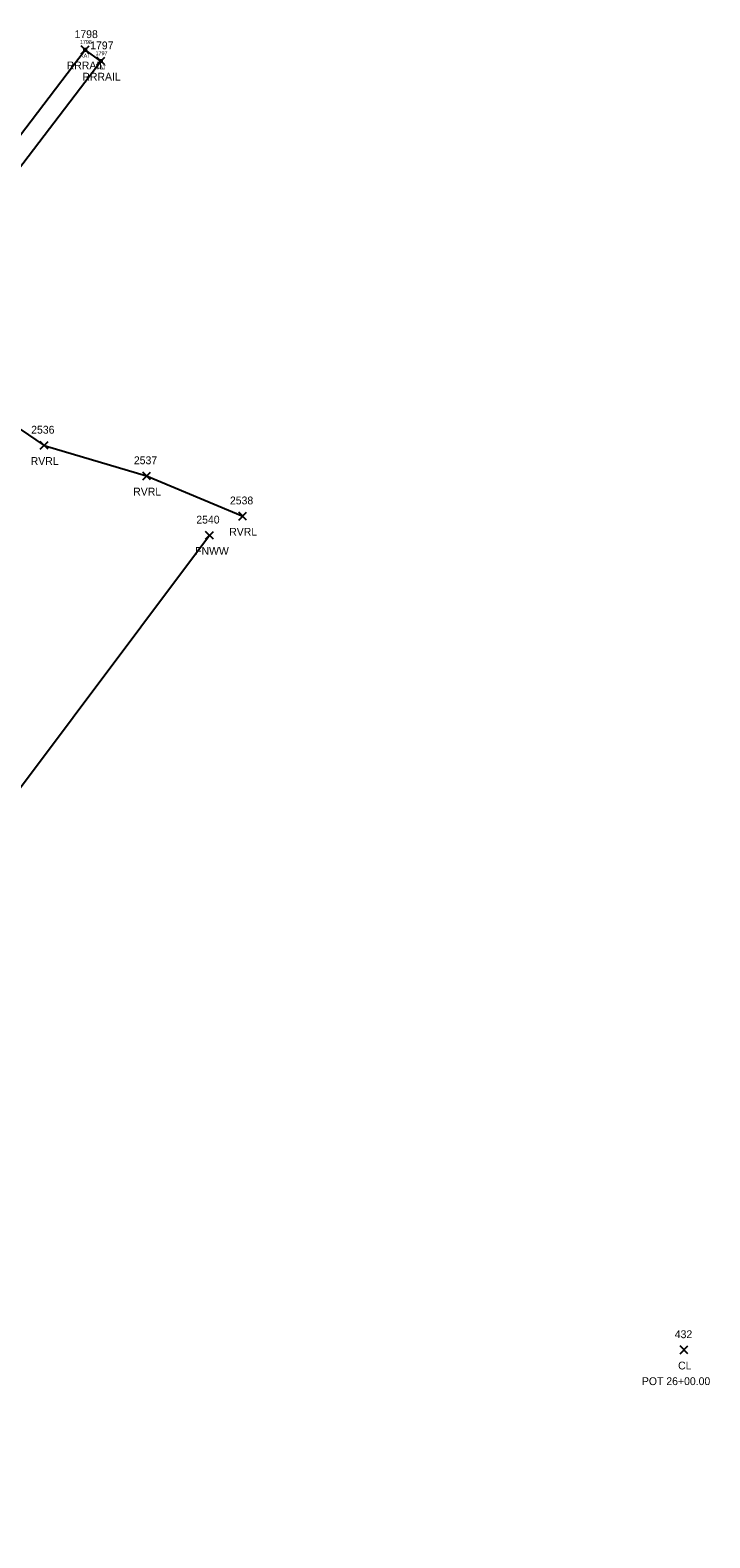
# Model space of a CAD drawing. Extents: x 1767353 to 1772625, y 740790 to 747702.
# Drawn here: x 1772451.2 to 1772625, y 747316.1 to 747701.7 of the extents above; entities that cross this region are included whole.
import ezdxf

# ---------------------------------------------------------------- set-up
doc = ezdxf.new("R2010")
doc.units = 0
for name, color, linetype in [('A_A', 7, 'Continuous'), ('A_C', 7, 'Continuous'), ('A_I', 7, 'Continuous'), ('A_TIC', 7, 'Continuous'), ('B_A', 7, 'Continuous'), ('B_I', 7, 'Continuous'), ('B_TIC', 7, 'Continuous'), ('BSUBM', 7, 'Continuous'), ('L_A', 7, 'Continuous'), ('L_I', 7, 'Continuous'), ('L_TIC', 7, 'Continuous'), ('LAWE', 7, 'Continuous'), ('LFNC', 7, 'Continuous'), ('R_A', 7, 'Continuous'), ('R_I', 7, 'Continuous'), ('R_TIC', 7, 'Continuous'), ('RR', 7, 'Continuous')]:
    doc.layers.add(name, color=color, linetype=linetype)

msp = doc.modelspace()

# ---------------------------------------------------------------- linework, layer by layer
at = {"layer": 'A_TIC'}
for points in [[(1772617.36, 747363.21), (1772619.36, 747365.21)], [(1772619.36, 747363.21), (1772617.36, 747365.21)]]:
    msp.add_lwpolyline(points, dxfattribs=at)
at = {"layer": 'B_TIC'}
for p, q in [((1772465.26, 747696.66), (1772465.33, 747696.66)), ((1772469.26, 747693.79), (1772469.33, 747693.79))]:
    msp.add_line(p, q, dxfattribs=at)
for points in [[(1772464.76, 747696.66), (1772465.76, 747696.66)], [(1772465.26, 747696.16), (1772465.26, 747697.16)], [(1772468.76, 747693.79), (1772469.76, 747693.79)], [(1772469.26, 747693.29), (1772469.26, 747694.29)]]:
    msp.add_lwpolyline(points, dxfattribs=at)
at = {"layer": 'BSUBM'}
msp.add_lwpolyline([(1772469.26, 747693.79), (1772465.26, 747696.66)], dxfattribs=at)
at = {"layer": 'L_TIC'}
for points in [[(1772453.79, 747594.51), (1772455.79, 747596.51)], [(1772455.79, 747594.51), (1772453.79, 747596.51)], [(1772479.99, 747586.69), (1772481.99, 747588.69)], [(1772481.99, 747586.69), (1772479.99, 747588.69)], [(1772504.54, 747576.42), (1772506.54, 747578.42)], [(1772506.54, 747576.42), (1772504.54, 747578.42)], [(1772496.04, 747571.52), (1772498.04, 747573.52)], [(1772498.04, 747571.52), (1772496.04, 747573.52)]]:
    msp.add_lwpolyline(points, dxfattribs=at)
at = {"layer": 'LAWE'}
msp.add_lwpolyline([(1772429.31, 747618.42), (1772438.46, 747606.53), (1772454.79, 747595.51), (1772480.99, 747587.69), (1772505.54, 747577.42)], dxfattribs=at)
at = {"layer": 'LFNC'}
msp.add_lwpolyline([(1772375.15, 747411.53), (1772444.65, 747502.58), (1772497.04, 747572.52)], dxfattribs=at)
at = {"layer": 'R_TIC'}
for points in [[(1772464.26, 747695.66), (1772466.26, 747697.66)], [(1772466.26, 747695.66), (1772464.26, 747697.66)], [(1772468.26, 747692.79), (1772470.26, 747694.79)], [(1772470.26, 747692.79), (1772468.26, 747694.79)]]:
    msp.add_lwpolyline(points, dxfattribs=at)
at = {"layer": 'RR'}
for points in [[(1771960.76, 746895.46), (1771976.57, 746936.04), (1771991.76, 746972.7), (1772003.71, 747000.43), (1772025.97, 747048.7), (1772044.45, 747086.9), (1772066.42, 747128.97), (1772087.05, 747166.47), (1772110.84, 747207.58), (1772133.43, 747244.66), (1772156.72, 747281.04), (1772175.9, 747310.14), (1772194.46, 747336.8), (1772219.05, 747370.3), (1772232.59, 747389.89), (1772256.2, 747421.67), (1772277.77, 747450.57), (1772416.44, 747632.57), (1772465.26, 747696.66)], [(1771963.49, 746888.34), (1771980.41, 746932.18), (1771994.59, 746967.04), (1772007.72, 746997.13), (1772029.49, 747045.02), (1772048.72, 747084.09), (1772070.77, 747126.16), (1772091.38, 747163.68), (1772115.23, 747205.31), (1772138.09, 747242.79), (1772160.69, 747278.1), (1772180.23, 747307.44), (1772199.65, 747335.62), (1772224.35, 747370.12), (1772238.38, 747389.48), (1772261.28, 747420.38), (1772281.38, 747447.15), (1772420.28, 747629.6), (1772469.26, 747693.79)]]:
    msp.add_lwpolyline(points, dxfattribs=at)

# ---------------------------------------------------------------- texts
at = {"layer": 'A_A'}
msp.add_text('CL', height=2, dxfattribs=at).set_placement((1772616.85, 747359.21))
at = {"layer": 'A_C'}
msp.add_text('POT 26+00.00', height=2, dxfattribs=at).set_placement((1772607.6, 747355.21))
at = {"layer": 'A_I'}
msp.add_text('432', height=2, dxfattribs=at).set_placement((1772616, 747367.21))
at = {"layer": 'B_A'}
for p in [(1772463.96, 747694.66), (1772467.96, 747691.79)]:
    msp.add_text('XAT', height=1, dxfattribs=at).set_placement(p)
at = {"layer": 'B_I'}
for s, p in [('1798', (1772463.91, 747698.16)), ('1797', (1772467.91, 747695.29))]:
    msp.add_text(s, height=1, dxfattribs=at).set_placement(p)
at = {"layer": 'L_A'}
for s, p in [('RVRL', (1772451.35, 747590.51)), ('RVRL', (1772477.56, 747582.69)), ('RVRL', (1772502.1, 747572.42)), ('FNWW', (1772493.38, 747567.52))]:
    msp.add_text(s, height=2, dxfattribs=at).set_placement(p)
at = {"layer": 'L_I'}
for s, p in [('2536', (1772451.47, 747598.51)), ('2537', (1772477.73, 747590.69)), ('2538', (1772502.28, 747580.42)), ('2540', (1772493.69, 747575.52))]:
    msp.add_text(s, height=2, dxfattribs=at).set_placement(p)
at = {"layer": 'R_A'}
for p in [(1772460.55, 747691.66), (1772464.55, 747688.79)]:
    msp.add_text('RRRAIL', height=2, dxfattribs=at).set_placement(p)
at = {"layer": 'R_I'}
for s, p in [('1798', (1772462.56, 747699.66)), ('1797', (1772466.56, 747696.79))]:
    msp.add_text(s, height=2, dxfattribs=at).set_placement(p)

doc.saveas('drawing.dxf')
